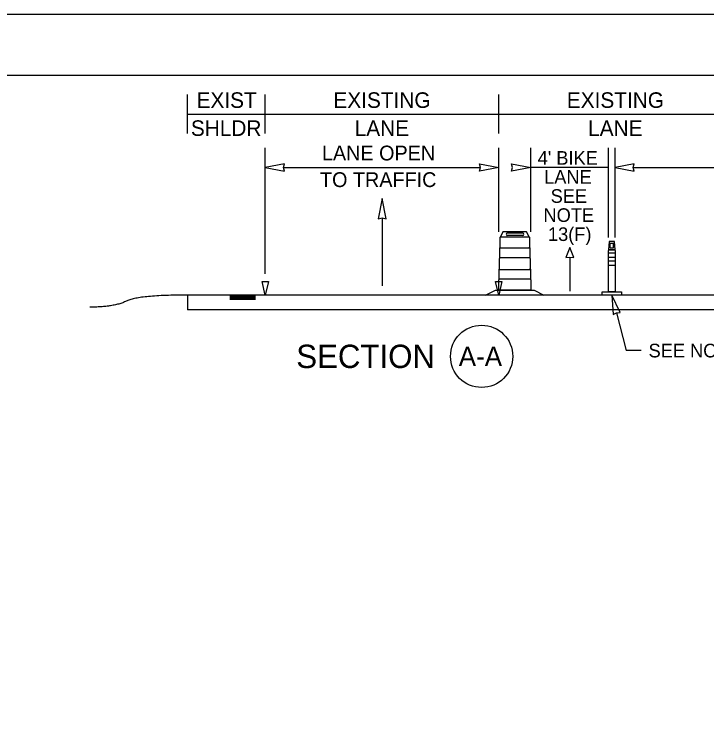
# Model space of a CAD drawing. Extents: x 99958 to 100136, y 99935 to 100013.
# Drawn here: x 100003.99 to 100007.548, y 99946.986 to 99950.687 of the extents above; entities that cross this region are included whole.
import ezdxf

# ---------------------------------------------------------------- set-up
doc = ezdxf.new("R2010")
doc.units = 0
for name, color, linetype in [('SH_GI_PlotLimits', 7, 'Continuous'), ('SH_GI_SheetBorder', 7, 'Continuous'), ('SH_TI_WZSectionCut', 7, 'Continuous'), ('TR_WZ_ArrowLeftStrRightTurn', 7, 'Continuous'), ('TR_WZ_TrafficSafetyDrumElev', 7, 'Continuous'), ('TR_WZ_TubularMarkerElev', 7, 'Continuous'), ('TR_WZ_WorkZoneDetails', 7, 'Continuous'), ('TR_WZ_WorkZoneTextCurrent', 7, 'Continuous')]:
    doc.layers.add(name, color=color, linetype=linetype)

msp = doc.modelspace()

# ---------------------------------------------------------------- linework, layer by layer
at = {"layer": 'SH_GI_PlotLimits'}
msp.add_lwpolyline([(99999.0625, 99939.6875), (100016.0625, 99939.6875), (100016.0625, 99950.6875), (99999.0625, 99950.6875)], close=True, dxfattribs=at)
at = {"layer": 'SH_GI_SheetBorder'}
msp.add_line((100000, 99950.375), (100015.75, 99950.375), dxfattribs=at)
at = {"layer": 'SH_TI_WZSectionCut'}
for p, q in [((100004.8794, 99950.075), (100004.8794, 99950.275)), ((100005.2794, 99950.075), (100005.2794, 99950.275)), ((100006.4794, 99950.075), (100006.4794, 99950.275)), ((100004.8794, 99950.175), (100005.2794, 99950.175)), ((100005.2794, 99950.175), (100006.4794, 99950.175)), ((100006.4794, 99950.175), (100007.6794, 99950.175)), ((100005.2794, 99949.3547), (100005.2794, 99950.001)), ((100006.4794, 99949.57), (100006.4794, 99950.001)), ((100006.6442, 99949.57), (100006.6442, 99950.001)), ((100007.0442, 99949.5408), (100007.0442, 99950.001)), ((100007.0775, 99949.5408), (100007.0775, 99950.001)), ((100005.3731, 99949.901), (100006.3857, 99949.901)), ((100007.0442, 99949.901), (100006.6442, 99949.901)), ((100007.1712, 99949.901), (100008.6794, 99949.901)), ((100008.6794, 99949.2449), (100004.8794, 99949.2449)), ((100004.8794, 99949.2449), (100004.8794, 99949.1699)), ((100005.0964, 99949.2397), (100005.2294, 99949.2397)), ((100005.0964, 99949.2341), (100005.2294, 99949.2341)), ((100005.0964, 99949.2284), (100005.2294, 99949.2284)), ((100005.0964, 99949.2232), (100005.2294, 99949.2232)), ((100008.6794, 99949.1699), (100004.8794, 99949.1699))]:
    msp.add_line(p, q, dxfattribs=at)
for points in [[(100005.2794, 99949.901), (100005.3777, 99949.8817), (100005.3731, 99949.901), (100005.3777, 99949.9203)], [(100006.4794, 99949.901), (100006.3811, 99949.8817), (100006.3857, 99949.901), (100006.3811, 99949.9203)], [(100006.6442, 99949.901), (100006.5459, 99949.8817), (100006.5504, 99949.901), (100006.5459, 99949.9203)], [(100007.0775, 99949.901), (100007.1758, 99949.8817), (100007.1712, 99949.901), (100007.1758, 99949.9203)], [(100005.2627, 99949.3147), (100005.296, 99949.3147), (100005.2794, 99949.2449)], [(100006.4627, 99949.3147), (100006.4961, 99949.3147), (100006.4794, 99949.2449)]]:
    msp.add_lwpolyline(points, close=True, dxfattribs=at)
msp.add_circle((100006.3916, 99948.93), 0.16, dxfattribs=at)
msp.add_open_spline([(100004.8794, 99949.2449), (100004.6282, 99949.2449), (100004.5027, 99949.1828), (100004.3773, 99949.1828)], degree=2, dxfattribs=at)
at = {"layer": 'TR_WZ_ArrowLeftStrRightTurn'}
for p, q in [((100005.8794, 99949.6418), (100005.8794, 99949.292)), ((100006.8442, 99949.4398), (100006.8442, 99949.2649))]:
    msp.add_line(p, q, dxfattribs=at)
for points in [[(100005.8794, 99949.742), (100005.8588, 99949.6369), (100005.8794, 99949.6418), (100005.9, 99949.6369)], [(100006.8442, 99949.4899), (100006.8236, 99949.4374), (100006.8442, 99949.4398), (100006.8648, 99949.4374)]]:
    msp.add_lwpolyline(points, close=True, dxfattribs=at)
at = {"layer": 'TR_WZ_TrafficSafetyDrumElev'}
for p, q in [((100006.4878, 99949.545), (100006.6358, 99949.545)), ((100006.4878, 99949.545), (100006.6358, 99949.545)), ((100006.5222, 99949.564), (100006.604, 99949.564)), ((100006.604, 99949.551), (100006.5222, 99949.551)), ((100006.4849, 99949.4871), (100006.6386, 99949.4871)), ((100006.4849, 99949.4372), (100006.4849, 99949.4871)), ((100006.6386, 99949.4871), (100006.6386, 99949.4372)), ((100006.6386, 99949.4372), (100006.4849, 99949.4372)), ((100006.4812, 99949.377), (100006.6423, 99949.377)), ((100006.4812, 99949.3271), (100006.4812, 99949.377)), ((100006.6423, 99949.377), (100006.6423, 99949.3271)), ((100006.6423, 99949.3271), (100006.4812, 99949.3271))]:
    msp.add_line(p, q, dxfattribs=at)
for points in [[(100006.6358, 99949.545), (100006.6226, 99949.57), (100006.5009, 99949.57), (100006.4878, 99949.545)], [(100006.4118, 99949.245), (100006.462, 99949.27), (100006.6615, 99949.27), (100006.7118, 99949.245)]]:
    msp.add_lwpolyline(points, close=True, dxfattribs=at)
for points in [[(100006.4868, 99949.4915), (100006.4868, 99949.543)], [(100006.4868, 99949.4915), (100006.4868, 99949.543)], [(100006.6368, 99949.543), (100006.6368, 99949.4915)], [(100006.6368, 99949.543), (100006.6368, 99949.4915)], [(100006.4849, 99949.4365), (100006.4849, 99949.4878)], [(100006.4849, 99949.4365), (100006.4849, 99949.4878)], [(100006.6386, 99949.4878), (100006.6386, 99949.4365)], [(100006.6386, 99949.4878), (100006.6386, 99949.4365)], [(100006.4831, 99949.3814), (100006.4831, 99949.4327)], [(100006.4831, 99949.3814), (100006.4831, 99949.4327)], [(100006.6405, 99949.4327), (100006.6405, 99949.3814)], [(100006.6405, 99949.4327), (100006.6405, 99949.3814)], [(100006.4812, 99949.3264), (100006.4812, 99949.3777)], [(100006.4812, 99949.3264), (100006.4812, 99949.3777)], [(100006.6423, 99949.3777), (100006.6423, 99949.3264)], [(100006.6423, 99949.3777), (100006.6423, 99949.3264)], [(100006.6442, 99949.3226), (100006.6442, 99949.27), (100006.4794, 99949.27), (100006.4794, 99949.3226)], [(100006.6442, 99949.3226), (100006.6442, 99949.27), (100006.4794, 99949.27), (100006.4794, 99949.3226)]]:
    msp.add_lwpolyline(points, dxfattribs=at)
for centre, major_axis, ratio, start_param, end_param in [((100006.488, 99949.5426), (0, 0.00249), 0.493438, 0.177149, 1.393647), ((100006.488, 99949.5426), (0, 0.00249), 0.493438, 0.177149, 1.393647), ((100006.5222, 99949.5575), (0, 0.0065), 0.570305, 0, 3.141593), ((100006.604, 99949.5575), (0, 0.0065), 0.570305, 3.141593, 6.283185), ((100006.6356, 99949.5426), (0, 0.00249), 0.493438, 4.889538, 6.106036), ((100006.6356, 99949.5426), (0, 0.00249), 0.493438, 4.889538, 6.106036), ((100006.4883, 99949.4846), (0, 0.00758), 0.493438, 0.4288, 1.141997), ((100006.4883, 99949.4846), (0, 0.00758), 0.493438, 0.4288, 1.141997), ((100006.6352, 99949.4846), (0, 0.00758), 0.493438, 5.141189, 5.854386), ((100006.6352, 99949.4846), (0, 0.00758), 0.493438, 5.141189, 5.854386), ((100006.4865, 99949.4296), (0, 0.00758), 0.493438, 0.4288, 1.141997), ((100006.4865, 99949.4296), (0, 0.00758), 0.493438, 0.4288, 1.141997), ((100006.6371, 99949.4296), (0, 0.00758), 0.493438, 5.141189, 5.854386), ((100006.6371, 99949.4296), (0, 0.00758), 0.493438, 5.141189, 5.854386), ((100006.4846, 99949.3745), (0, 0.00758), 0.493438, 0.4288, 1.141997), ((100006.4846, 99949.3745), (0, 0.00758), 0.493438, 0.4288, 1.141997), ((100006.6389, 99949.3745), (0, 0.00758), 0.493438, 5.141189, 5.854386), ((100006.6389, 99949.3745), (0, 0.00758), 0.493438, 5.141189, 5.854386), ((100006.4828, 99949.3195), (0, 0.00758), 0.493438, 0.4288, 1.141997), ((100006.4828, 99949.3195), (0, 0.00758), 0.493438, 0.4288, 1.141997), ((100006.6408, 99949.3195), (0, 0.00758), 0.493438, 5.141189, 5.854386), ((100006.6408, 99949.3195), (0, 0.00758), 0.493438, 5.141189, 5.854386)]:
    msp.add_ellipse(centre, major_axis=major_axis, ratio=ratio, start_param=start_param, end_param=end_param, dxfattribs=at)
at = {"layer": 'TR_WZ_TubularMarkerElev'}
for p, q in [((100007.0692, 99949.5106), (100007.0517, 99949.5106)), ((100007.0442, 99949.4619), (100007.0775, 99949.4619)), ((100007.0442, 99949.4373), (100007.0442, 99949.4619)), ((100007.0772, 99949.4783), (100007.0444, 99949.4783)), ((100007.0517, 99949.4884), (100007.0692, 99949.4884)), ((100007.0775, 99949.4619), (100007.0775, 99949.4373)), ((100007.0775, 99949.4373), (100007.0442, 99949.4373)), ((100007.0442, 99949.3964), (100007.0442, 99949.421)), ((100007.0442, 99949.421), (100007.0775, 99949.421)), ((100007.0775, 99949.421), (100007.0775, 99949.3964)), ((100007.0775, 99949.3964), (100007.0442, 99949.3964)), ((100007.0108, 99949.2449), (100007.0108, 99949.2613)), ((100007.1108, 99949.2449), (100007.0108, 99949.2449)), ((100007.1108, 99949.2613), (100007.1108, 99949.2449))]:
    msp.add_line(p, q, dxfattribs=at)
msp.add_lwpolyline([(100007.0772, 99949.4783), (100007.0742, 99949.5208), (100007.0472, 99949.5208), (100007.0444, 99949.4783)], close=True, dxfattribs=at)
for points in [[(100007.0775, 99949.2613), (100007.0442, 99949.2613), (100007.0442, 99949.4741)], [(100007.0775, 99949.2613), (100007.0442, 99949.2613), (100007.0442, 99949.4741)], [(100007.0444, 99949.4783), (100007.0772, 99949.4783), (100007.0444, 99949.4783), (100007.0772, 99949.4783)], [(100007.0444, 99949.4783), (100007.0772, 99949.4783), (100007.0444, 99949.4783), (100007.0772, 99949.4783)], [(100007.0775, 99949.4741), (100007.0775, 99949.2613)], [(100007.0775, 99949.4741), (100007.0775, 99949.2613)], [(100007.0108, 99949.2613), (100007.0442, 99949.2613), (100007.0775, 99949.2613), (100007.1108, 99949.2613)]]:
    msp.add_lwpolyline(points, dxfattribs=at)
for centre, major_axis, ratio, start_param, end_param in [((100007.0517, 99949.4995), (0, 0.0111), 0.071484, 0, 3.141593), ((100007.0692, 99949.4995), (0, 0.0111), 0.071484, 3.141593, 6.283185), ((100007.0444, 99949.4732), (0, 0.00512), 0.053405, 0.177149, 1.393647), ((100007.0444, 99949.4732), (0, 0.00512), 0.053405, 0.177149, 1.393647), ((100007.0772, 99949.4732), (0, 0.00512), 0.053405, 4.889538, 6.106036), ((100007.0772, 99949.4732), (0, 0.00512), 0.053405, 4.889538, 6.106036)]:
    msp.add_ellipse(centre, major_axis=major_axis, ratio=ratio, start_param=start_param, end_param=end_param, dxfattribs=at)
at = {"layer": 'TR_WZ_WorkZoneDetails'}
for p in [(100007.0844, 99949.1542), (100007.2111, 99948.9596)]:
    msp.add_line(p, (100007.1349, 99948.9596), dxfattribs=at)
msp.add_lwpolyline([(100007.0608, 99949.2449), (100007.0669, 99949.145), (100007.0844, 99949.1542), (100007.1042, 99949.1547)], close=True, dxfattribs=at)

# ---------------------------------------------------------------- texts
at = {"layer": 'SH_TI_WZSectionCut'}
for s, height, p in [('EXIST', 0.08, (100004.9261, 99950.207)), ('EXISTING', 0.08, (100005.6296, 99950.207)), ('EXISTING', 0.08, (100006.8296, 99950.207)), ('SHLDR', 0.08, (100004.8969, 99950.063)), ('LANE', 0.08, (100005.739, 99950.063)), ('LANE', 0.08, (100006.939, 99950.063)), ('SECTION', 0.12, (100005.4385, 99948.87)), ('A-A', 0.1, (100006.2738, 99948.88))]:
    msp.add_text(s, height=height, rotation=360, dxfattribs=at).set_placement(p)
for s, height, p in [('LANE OPEN', 0.076, (100005.5707, 99949.937)), ("4' BIKE", 0.07, (100006.6796, 99949.915)), ('TO TRAFFIC', 0.076, (100005.5606, 99949.8002)), ('LANE', 0.07, (100006.7128, 99949.817)), ('SEE', 0.07, (100006.7464, 99949.719)), ('NOTE', 0.07, (100006.7095, 99949.621)), ('13(F)', 0.07, (100006.7326, 99949.523))]:
    msp.add_text(s, height=height, dxfattribs=at).set_placement(p)
at = {"layer": 'TR_WZ_WorkZoneTextCurrent'}
msp.add_text('SEE NOTE 8', height=0.07, dxfattribs=at).set_placement((100007.2498, 99948.9246))

doc.saveas('drawing.dxf')
